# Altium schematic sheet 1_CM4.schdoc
size 431 x 309 mm; Symbol: Sheet-Symbol_A4; Device: Sheet-Symbol_A4; Company: EasyEDA.com; Drawed: EasyEDA Pro; Reviewed: EasyEDA Pro; Version: V0.1; Page Size: A4; @Project Name: CM4-Nvme-NAS-main; @Page Count: 6; @Update Date: 2023-05-18; @Create Date: 2023-04-29; @Schematic Name: RaspberryPiNVMeNAS; Part Number: JLCPCB-002; @Page No: 4; @Page Name: CM4
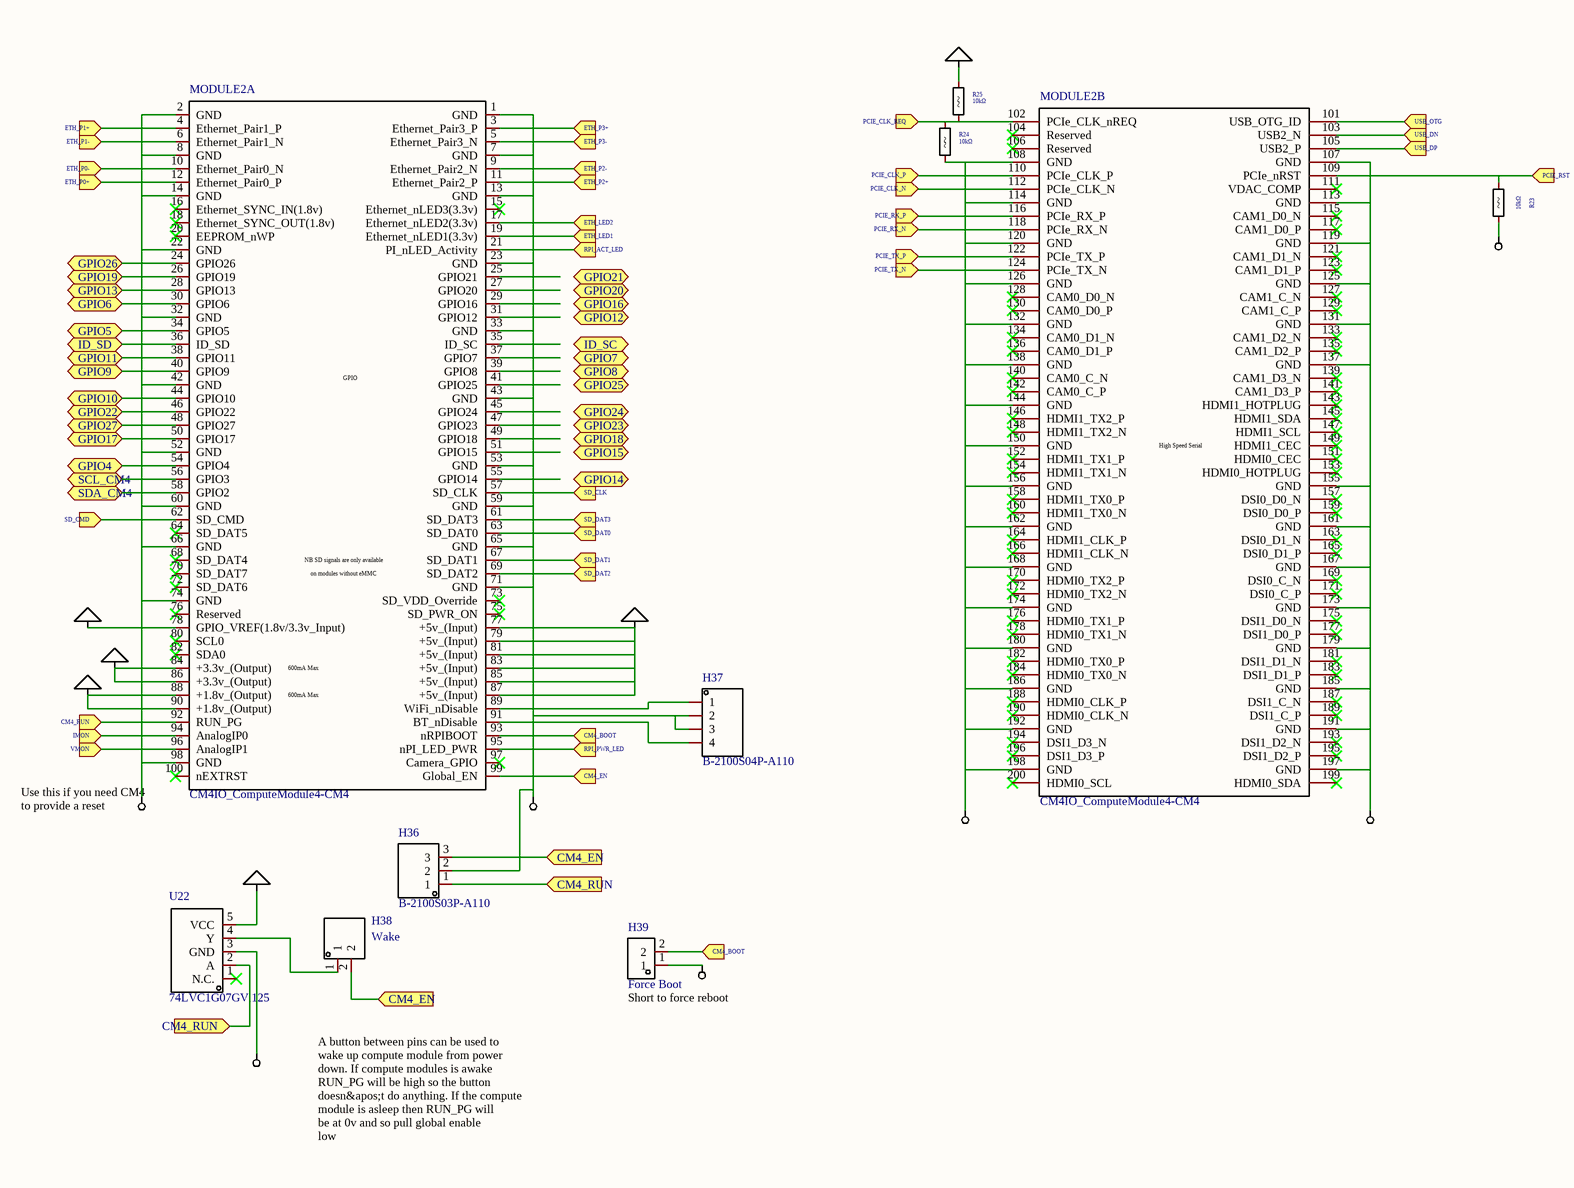
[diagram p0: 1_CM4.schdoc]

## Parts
H36  B-2100S03P-A110  [HDR-TH_3P-P2.54-V-M-1]
H37  B-2100S04P-A110  [HDR-TH_4P-P2.54-V-M]
H38  Wake  [HDR-TH_2P-P2.54-V-M-1]
H39  Force Boot  [HDR-SMD_2P-P2.54-V-M-S4.8]
MODULE2  CM4IO_ComputeModule4-CM4  (parts A,B of 2)
R23  10kΩ  [R0402]
R24  10kΩ  [R0402]
R25  10kΩ  [R0402]
U22  74LVC1G07GV,125  [SOT-753_L3.1-W1.7-P0.95-LS3.0-BR]

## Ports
CM4_BOOT (in), CM4_EN (in), CM4_RUN (in), ETH_LED1 (in), ETH_LED2 (in), ETH_P0+ (in), ETH_P0- (in), ETH_P1+ (in), ETH_P1- (in), ETH_P2+ (in), ETH_P2- (in), ETH_P3+ (in), ETH_P3- (in), GPIO4 (bidir), GPIO5 (bidir), GPIO6 (bidir), GPIO7 (bidir), GPIO8 (bidir), GPIO9 (bidir), GPIO10 (bidir), GPIO11 (bidir), GPIO12 (bidir), GPIO13 (bidir), GPIO14 (bidir), GPIO15 (bidir), GPIO16 (bidir), GPIO17 (bidir), GPIO18 (bidir), GPIO19 (bidir), GPIO20 (bidir), GPIO21 (bidir), GPIO22 (bidir), GPIO23 (bidir), GPIO24 (bidir), GPIO25 (bidir), GPIO26 (bidir), GPIO27 (bidir), ID_SC (bidir), ID_SD (bidir), IMON (in), PCIE_CLK_N (in), PCIE_CLK_P (in), PCIE_CLK_REQ (in), PCIE_RST (in), PCIE_RX_N (in), PCIE_RX_P (in), PCIE_TX_N (in), PCIE_TX_P (in), RPI_ACT_LED (in), RPI_PWR_LED (in), SCL_CM4 (bidir), SD_CLK (in), SD_CMD (in), SD_DAT0 (in), SD_DAT1 (in), SD_DAT2 (in), SD_DAT3 (in), SDA_CM4 (bidir), USB_DN (in), USB_DP (in), USB_OTG (in), VMON (in)

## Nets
POWER_+1V8: MODULE2.88(+1.8v_(Output)) MODULE2.90(+1.8v_(Output))
POWER_+3.3V: MODULE2.78(GPIO_VREF(1.8v/3.3v_Input)) MODULE2.84(+3.3v_(Output)) MODULE2.86(+3.3v_(Output)) R25.1
POWER_+5V: MODULE2.77(+5v_(Input)) MODULE2.79(+5v_(Input)) MODULE2.81(+5v_(Input)) MODULE2.83(+5v_(Input)) MODULE2.85(+5v_(Input)) MODULE2.87(+5v_(Input)) U22.5(VCC)
POWER_GND: H36.2 H37.2 H37.3 H39.1 MODULE2.1(GND) MODULE2.2(GND) MODULE2.7(GND) MODULE2.8(GND) MODULE2.13(GND) MODULE2.14(GND) MODULE2.22(GND) MODULE2.23(GND) MODULE2.32(GND) MODULE2.33(GND) MODULE2.42(GND) MODULE2.43(GND) MODULE2.52(GND) MODULE2.53(GND) MODULE2.59(GND) MODULE2.60(GND) MODULE2.65(GND) MODULE2.66(GND) MODULE2.71(GND) MODULE2.74(GND) MODULE2.98(GND) MODULE2.107(GND) MODULE2.108(GND) MODULE2.113(GND) MODULE2.114(GND) MODULE2.119(GND) MODULE2.120(GND) MODULE2.125(GND) MODULE2.126(GND) MODULE2.131(GND) MODULE2.132(GND) MODULE2.137(GND) MODULE2.138(GND) MODULE2.144(GND) MODULE2.150(GND) MODULE2.155(GND) MODULE2.156(GND) MODULE2.161(GND) MODULE2.162(GND) MODULE2.167(GND) MODULE2.168(GND) MODULE2.173(GND) MODULE2.174(GND) MODULE2.179(GND) MODULE2.180(GND) MODULE2.185(GND) MODULE2.186(GND) MODULE2.191(GND) MODULE2.192(GND) MODULE2.197(GND) MODULE2.198(GND) R23.2 R24.2 U22.3(GND)
CM4_BOOT: H39.2 MODULE2.93(nRPIBOOT) ; port CM4_BOOT
CM4_EN: H36.3 H38.2 MODULE2.99(Global_EN) ; port CM4_EN
CM4_RUN: H36.1 MODULE2.92(RUN_PG) U22.2(A) ; port CM4_RUN
ETH_LED1: MODULE2.19(Ethernet_nLED1(3.3v)) ; port ETH_LED1
ETH_LED2: MODULE2.17(Ethernet_nLED2(3.3v)) ; port ETH_LED2
ETH_P0+: MODULE2.12(Ethernet_Pair0_P) ; port ETH_P0+
ETH_P0-: MODULE2.10(Ethernet_Pair0_N) ; port ETH_P0-
ETH_P1+: MODULE2.4(Ethernet_Pair1_P) ; port ETH_P1+
ETH_P1-: MODULE2.6(Ethernet_Pair1_N) ; port ETH_P1-
ETH_P2+: MODULE2.11(Ethernet_Pair2_P) ; port ETH_P2+
ETH_P2-: MODULE2.9(Ethernet_Pair2_N) ; port ETH_P2-
ETH_P3+: MODULE2.3(Ethernet_Pair3_P) ; port ETH_P3+
ETH_P3-: MODULE2.5(Ethernet_Pair3_N) ; port ETH_P3-
GPIO4: MODULE2.54(GPIO4) ; port GPIO4
GPIO5: MODULE2.34(GPIO5) ; port GPIO5
GPIO6: MODULE2.30(GPIO6) ; port GPIO6
GPIO9: MODULE2.40(GPIO9) ; port GPIO9
GPIO10: MODULE2.44(GPIO10) ; port GPIO10
GPIO11: MODULE2.38(GPIO11) ; port GPIO11
GPIO13: MODULE2.28(GPIO13) ; port GPIO13
GPIO17: MODULE2.50(GPIO17) ; port GPIO17
GPIO19: MODULE2.26(GPIO19) ; port GPIO19
GPIO22: MODULE2.46(GPIO22) ; port GPIO22
GPIO26: MODULE2.24(GPIO26) ; port GPIO26
GPIO27: MODULE2.48(GPIO27) ; port GPIO27
ID_SD: MODULE2.36(ID_SD) ; port ID_SD
IMON: MODULE2.94(AnalogIP0) ; port IMON
PCIE_CLK_N: MODULE2.112(PCIe_CLK_N) ; port PCIE_CLK_N
PCIE_CLK_P: MODULE2.110(PCIe_CLK_P) ; port PCIE_CLK_P
PCIE_CLK_REQ: MODULE2.102(PCIe_CLK_nREQ) R24.1 R25.2 ; port PCIE_CLK_REQ
PCIE_RST: MODULE2.109(PCIe_nRST) R23.1 ; port PCIE_RST
PCIE_RX_N: MODULE2.118(PCIe_RX_N) ; port PCIE_RX_N
PCIE_RX_P: MODULE2.116(PCIe_RX_P) ; port PCIE_RX_P
PCIE_TX_N: MODULE2.124(PCIe_TX_N) ; port PCIE_TX_N
PCIE_TX_P: MODULE2.122(PCIe_TX_P) ; port PCIE_TX_P
RPI_ACT_LED: MODULE2.21(PI_nLED_Activity) ; port RPI_ACT_LED
RPI_PWR_LED: MODULE2.95(nPI_LED_PWR) ; port RPI_PWR_LED
SCL_CM4: MODULE2.56(GPIO3) ; port SCL_CM4
SD_CLK: MODULE2.57(SD_CLK) ; port SD_CLK
SD_CMD: MODULE2.62(SD_CMD) ; port SD_CMD
SD_DAT0: MODULE2.63(SD_DAT0) ; port SD_DAT0
SD_DAT1: MODULE2.67(SD_DAT1) ; port SD_DAT1
SD_DAT2: MODULE2.69(SD_DAT2) ; port SD_DAT2
SD_DAT3: MODULE2.61(SD_DAT3) ; port SD_DAT3
SDA_CM4: MODULE2.58(GPIO2) ; port SDA_CM4
USB_DN: MODULE2.103(USB2_N) ; port USB_DN
USB_DP: MODULE2.105(USB2_P) ; port USB_DP
USB_OTG: MODULE2.101(USB_OTG_ID) ; port USB_OTG
VMON: MODULE2.96(AnalogIP1) ; port VMON
NetH37_1: H37.1 MODULE2.89(WiFi_nDisable)
NetH37_4: H37.4 MODULE2.91(BT_nDisable)
NetH38_1: H38.1 U22.4(Y)

Not connected (* = marked no-connect by the designer): MODULE2 15(Ethernet_nLED3(3.3v))* 16(Ethernet_SYNC_IN(1.8v))* 18(Ethernet_SYNC_OUT(1.8v))* 20(EEPROM_nWP)* 25(GPIO21) 27(GPIO20) 29(GPIO16) 31(GPIO12) 35(ID_SC) 37(GPIO7) 39(GPIO8) 41(GPIO25) 45(GPIO24) 47(GPIO23) 49(GPIO18) 51(GPIO15) 55(GPIO14) 64(SD_DAT5)* 68(SD_DAT4)* 70(SD_DAT7)* 72(SD_DAT6)* 73(SD_VDD_Override)* 75(SD_PWR_ON)* 76(Reserved)* 80(SCL0)* 82(SDA0)* 97(Camera_GPIO)* 100(nEXTRST)* 104(Reserved)* 106(Reserved)* 111(VDAC_COMP)* 115(CAM1_D0_N)* 117(CAM1_D0_P)* 121(CAM1_D1_N)* 123(CAM1_D1_P)* 127(CAM1_C_N)* 128(CAM0_D0_N)* 129(CAM1_C_P)* 130(CAM0_D0_P)* 133(CAM1_D2_N)* 134(CAM0_D1_N)* 135(CAM1_D2_P)* 136(CAM0_D1_P)* 139(CAM1_D3_N)* 140(CAM0_C_N)* 141(CAM1_D3_P)* 142(CAM0_C_P)* 143(HDMI1_HOTPLUG)* 145(HDMI1_SDA)* 146(HDMI1_TX2_P)* 147(HDMI1_SCL)* 148(HDMI1_TX2_N)* 149(HDMI1_CEC)* 151(HDMI0_CEC)* 152(HDMI1_TX1_P)* 153(HDMI0_HOTPLUG)* 154(HDMI1_TX1_N)* 157(DSI0_D0_N)* 158(HDMI1_TX0_P)* 159(DSI0_D0_P)* 160(HDMI1_TX0_N)* 163(DSI0_D1_N)* 164(HDMI1_CLK_P)* 165(DSI0_D1_P)* 166(HDMI1_CLK_N)* 169(DSI0_C_N)* 170(HDMI0_TX2_P)* 171(DSI0_C_P)* 172(HDMI0_TX2_N)* 175(DSI1_D0_N)* 176(HDMI0_TX1_P)* 177(DSI1_D0_P)* 178(HDMI0_TX1_N)* 181(DSI1_D1_N)* 182(HDMI0_TX0_P)* 183(DSI1_D1_P)* 184(HDMI0_TX0_N)* 187(DSI1_C_N)* 188(HDMI0_CLK_P)* 189(DSI1_C_P)* 190(HDMI0_CLK_N)* 193(DSI1_D2_N)* 194(DSI1_D3_N)* 195(DSI1_D2_P)* 196(DSI1_D3_P)* 199(HDMI0_SDA)* 200(HDMI0_SCL)*; U22 1(N.C.)*

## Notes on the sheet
- (near MODULE2) Use this if you need CM4
  to provide a reset
- (near H39) Short to force reboot
- A button between pins can be used to
  wake up compute module from power
  down. If compute modules is awake
  RUN_PG will be high so the button
  doesn&apos;t do anything. If the compute
  module is asleep then RUN_PG will
  be at 0v and so pull global enable
  low

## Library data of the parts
H36 = B-2100S03P-A110: Number of Rows:单排 Number of Pins:3 Pitch:2.54mm Pin Structure:1x3P Row Spacing:- Mounting Type:Straight Circluar Pins/Square Pins:- Current Rating (Max):- Voltage Rating (Max):- Length of Mating Pin:6mm Insulation Height:2.54mm Length of End Connection Pi; Manufacturer: Ckmtw(灿科盟); Symbol: 210S-1*3P L=11.6MMGold-plated black; Add into BOM: yes; Pitch: 2.54mm; Pin Structure: 1x3P
H37 = B-2100S04P-A110: Number of Rows:单排 Number of Pins:4 Pitch:2.54mm Pin Structure:1x4P Row Spacing:- Mounting Type:Straight Circluar Pins/Square Pins:- Current Rating (Max):- Voltage Rating (Max):- Length of Mating Pin:6mm Insulation Height:2.54mm Length of End Connection Pi; Manufacturer: Ckmtw(灿科盟); Symbol: Header-Male-2.54_1x4; Add into BOM: yes; Pitch: 2.54mm; Pin Structure: 1x4P
H38 = B-2100S02P-A110: Number of Rows:单排 Number of Pins:2 Pitch:2.54mm Pin Structure:1x2P Row Spacing:- Mounting Type:Straight Circluar Pins/Square Pins:- Current Rating (Max):- Voltage Rating (Max):- Length of Mating Pin:6mm Insulation Height:2.54mm Length of End Connection Pi; Manufacturer: Ckmtw(灿科盟); Symbol: 210S-1*2P L=11.6MMGold-plated black; Add into BOM: yes; Pitch: 2.54mm; Pin Structure: 1x2P
H39 = X6511WVS-02H-C60D48R1_C780060: Number of Rows:单排 Number of Pins:2 Pitch:2.54mm Pin Structure:1x2P Row Spacing:- Mounting Type:Brick nogging Circluar Pins/Square Pins:Square Pins Current Rating (Max):3A Voltage Rating (Max):250V Length of Mating Pin:6mm Insulation Height:2.5mm Length of; Manufacturer: XKB Connectivity(中国星坤); Symbol: X6511WVS-02H-C60D48-R1; Add into BOM: yes; Pitch: 2.54mm; Pin Structure: 1x2P; Current Rating (Max): 3A; Voltage Rating (Max): 250V; Welding Temperature (Max): 260℃
MODULE2 = CM4IO_ComputeModule4-CM4: Part Description: 100 Position Connector Receptacle, Center Strip Contacts Surface Mount Gold; Add into BOM: yes; Field4: Hirose; Field5: 2x DF40C-100DS-0.4V; Field6: 2off DF40C-100DS-0.4V
R23-R25 = 0402WGF1002TCE: Type:Thick Film Resistors Resistance: Tolerance:±1% Tolerance:±1% Power(Watts): Temperature Coefficient:±100ppm/℃ Temperature Coefficient:±100ppm/℃ Overload Voltage (Max): Operating Temperature Range:-55℃~+155℃ Operating Temperature Range:-55℃~+155℃; Manufacturer: UNI-ROYAL(厚声); Add into BOM: yes; Tolerance: ±1%; Origin Footprint: R_0402_1005Metric
U22 = 74LVC1G07GV,125: Manufacturer: Nexperia(安世); Add into BOM: yes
